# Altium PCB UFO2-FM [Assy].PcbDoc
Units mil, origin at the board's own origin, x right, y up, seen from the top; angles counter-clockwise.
Board outline 2125.98 x 1889.76 mil, 2 copper layers (Top Layer, Bottom Layer), stack 63.824 mil thick; 0 components, 51 nets, 0 pads, 0 vias.
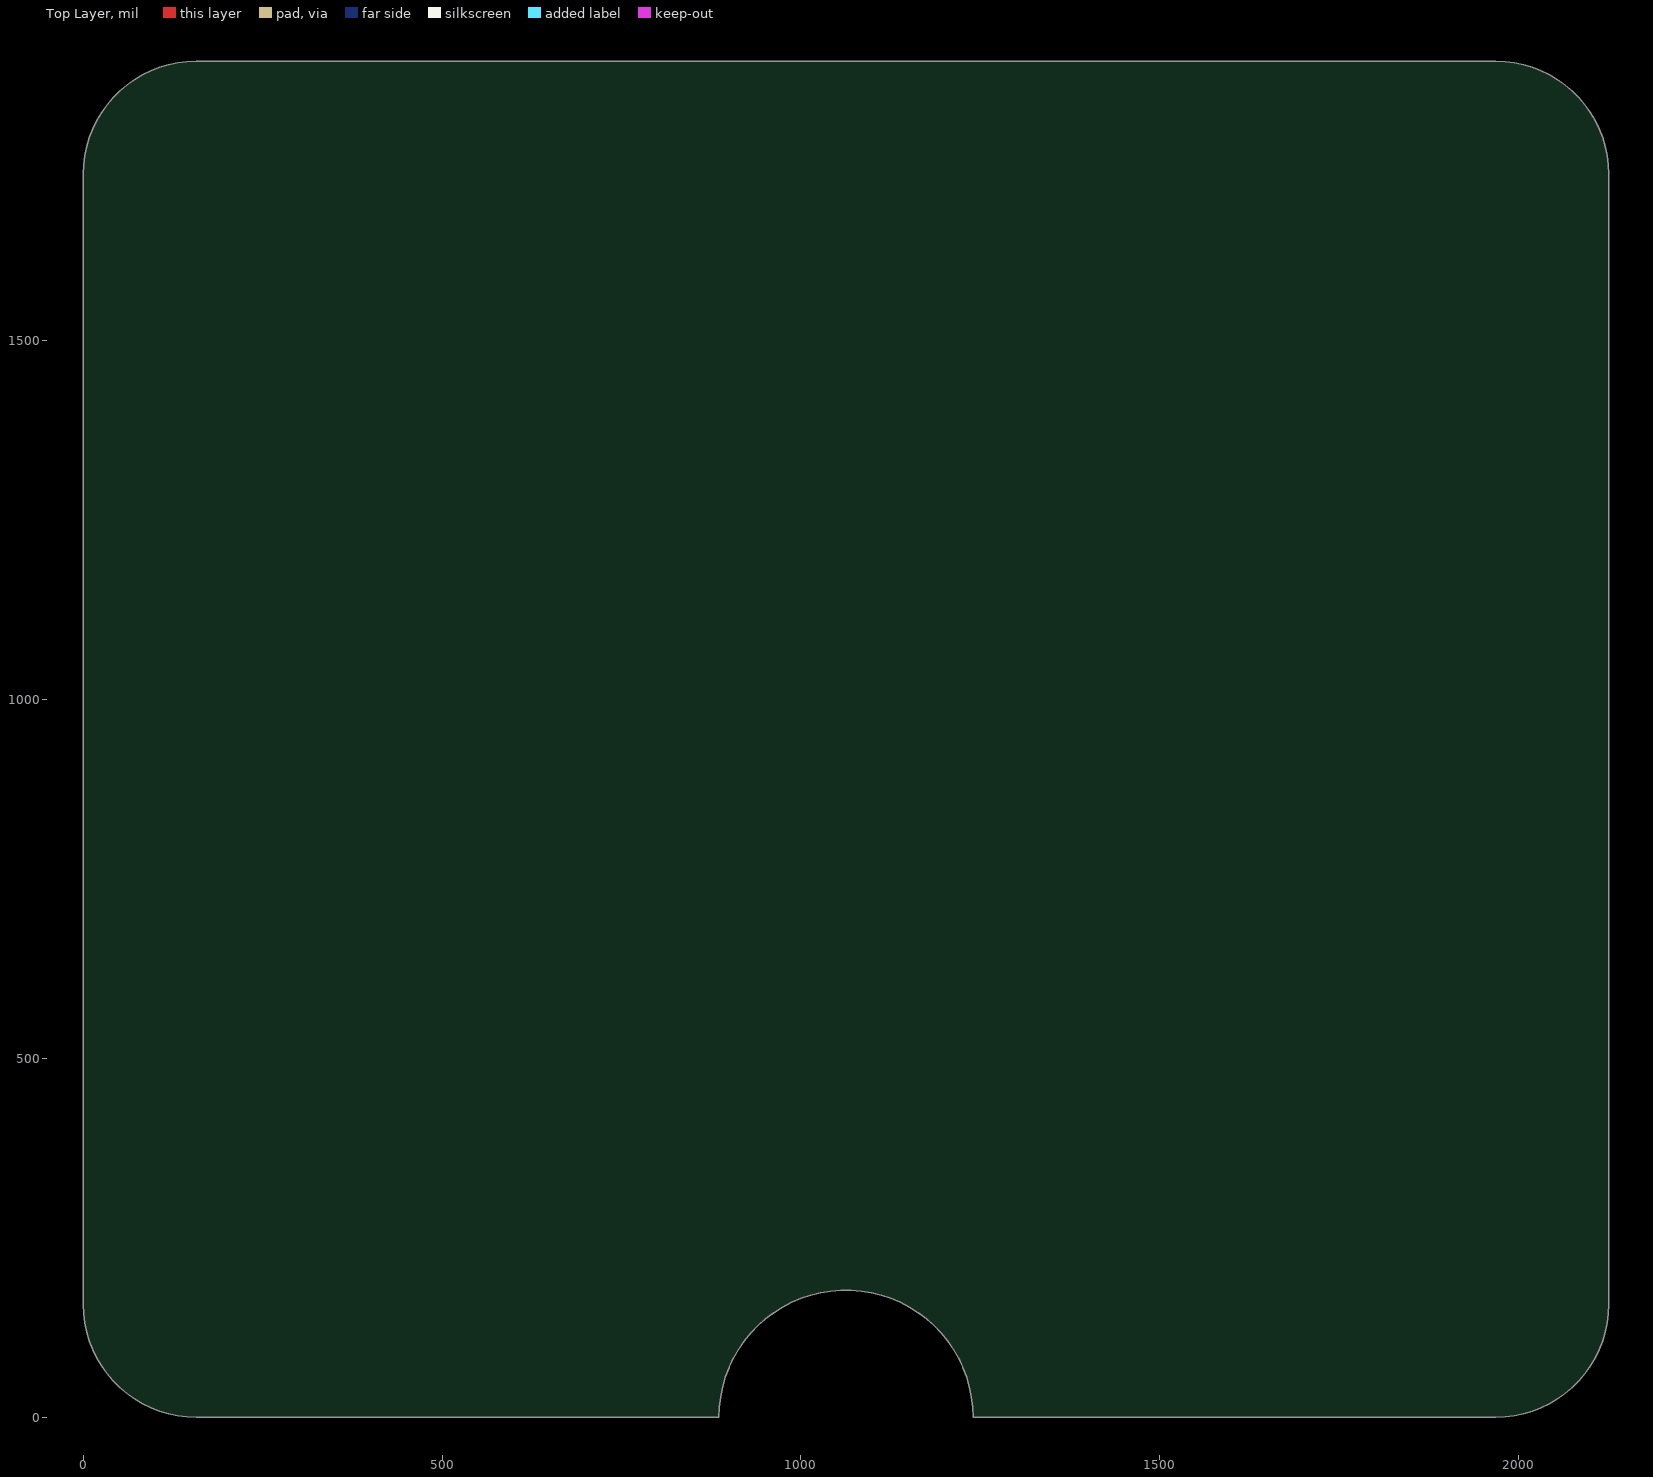
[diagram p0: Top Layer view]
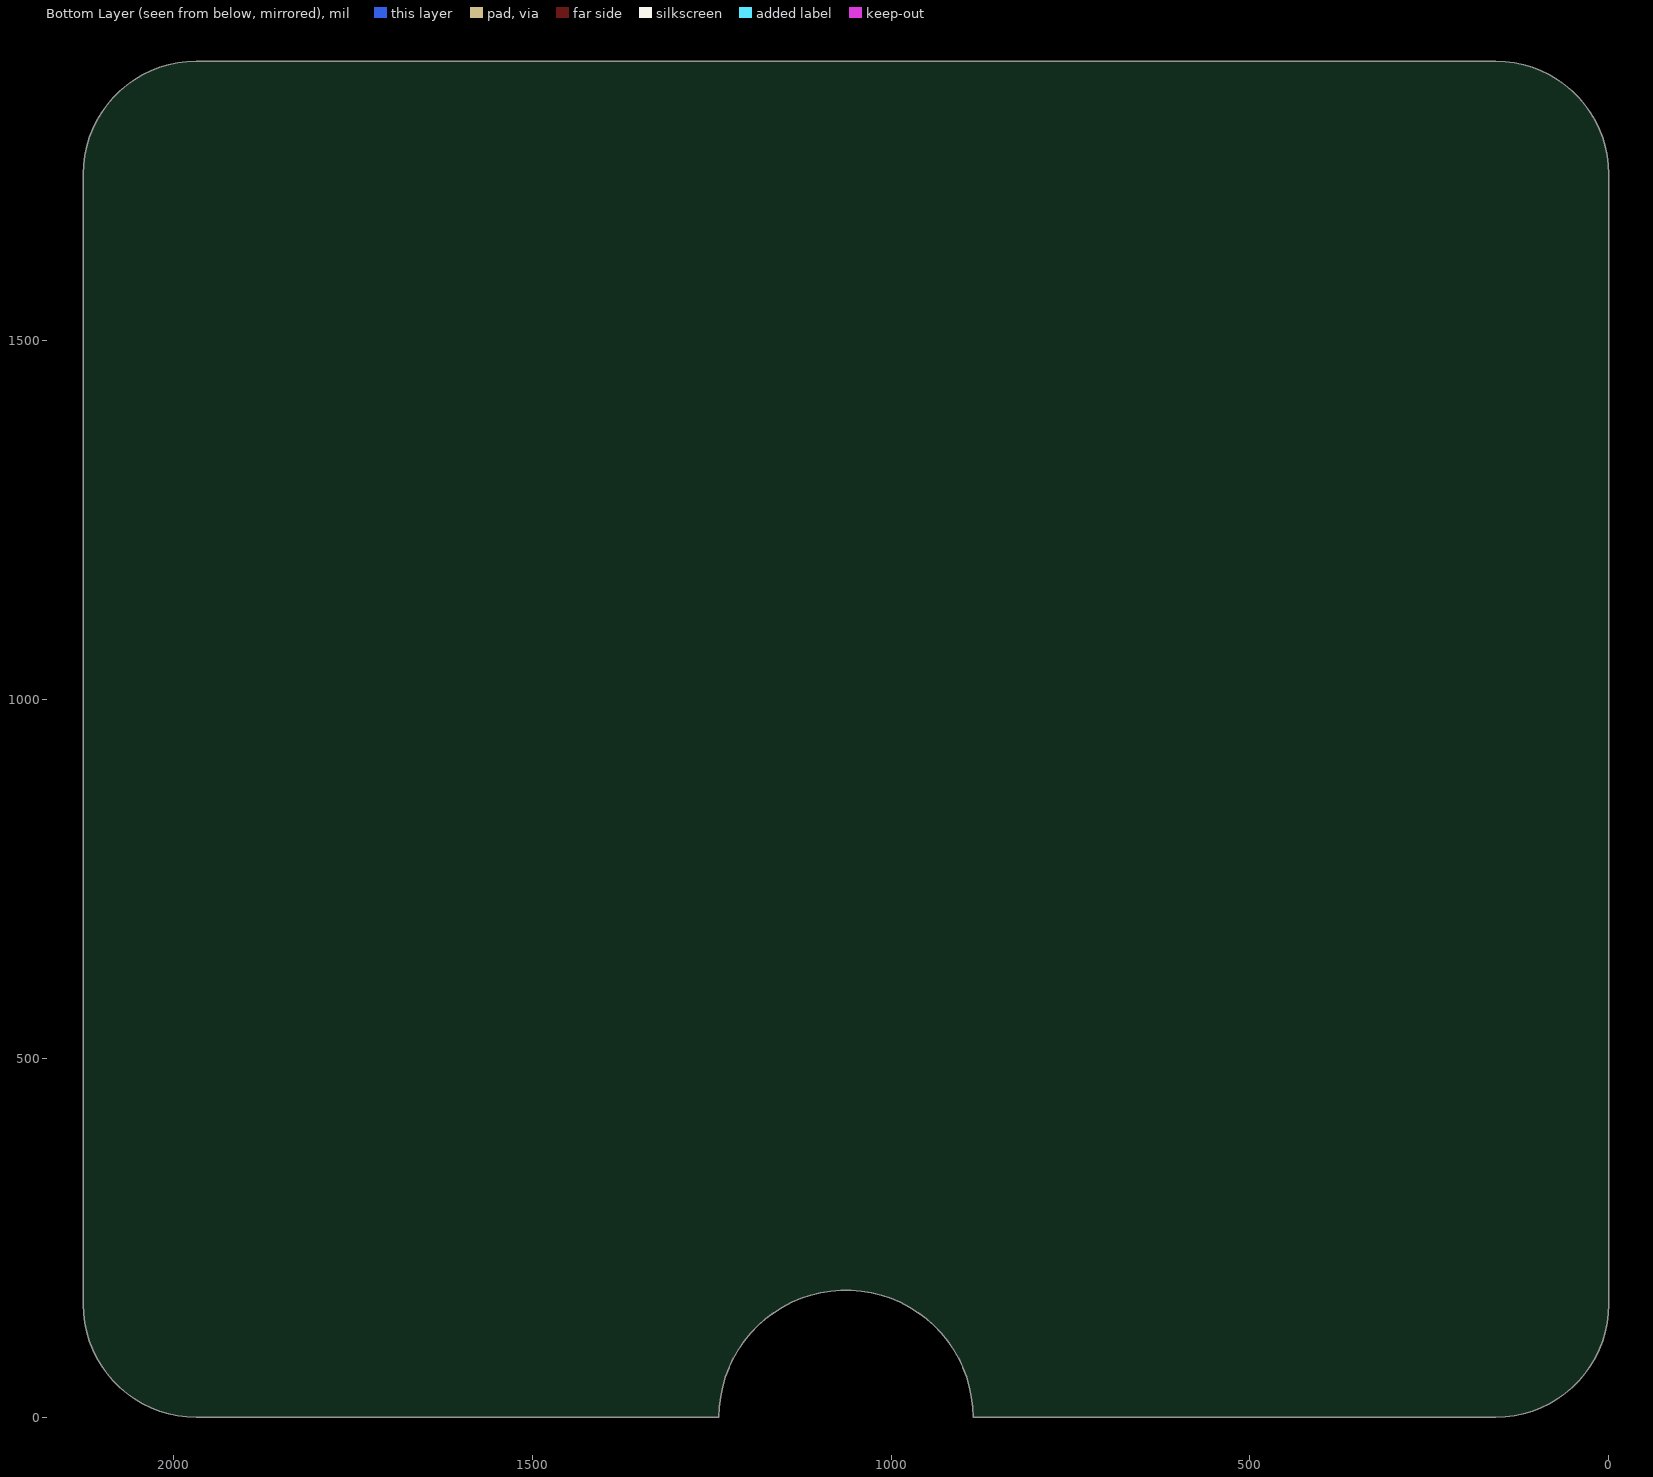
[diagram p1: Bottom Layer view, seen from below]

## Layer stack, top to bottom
Top Layer: signal copper 1.4
Dielectric: prepreg 61.0236, FR-4, Dk 4.2
Bottom Layer: signal copper 1.4

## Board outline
0,157.48 ccw(c157.48,157.48) 157.48,0 157.48,0.01 885.83,0 cw(c1062.99,0) 1240.16,0 1968.5,0 ccw(c1968.5,157.48) 2125.98,157.48 2125.98,1732.28 ccw(c1968.5,1732.28) 1968.5,1889.76 157.48,1889.76 ccw(c157.48,1732.28) 0,1732.28

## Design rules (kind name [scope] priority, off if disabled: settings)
Clearance [All] p1: gap=6.69
ComponentClearance [All] p1: gap=0 collisioncheckmode=3 verticalgap=1 showdistances=FALSE
FabricationTestPointUsage TestPointUsage [All] p1: valid=0 allowmultiple=FALSE
FabricationTestpoint Testpoint [All] p1: side=3 testpointundercomponent=TRUE minsize=40 maxsize=100 preferedsize=60 minholesize=0 maxholesize=40 preferedholesize=32 testpointgrid=1 allowsidetop=TRUE allowsidebottom=TRUE usegrid=TRUE gridtolerance=0.01
HoleSize [All] p1: absolutevalues=TRUE maxlimit=196.85 minlimit=9.84 maxpercent=80.000 minpercent=20.000
Length "Schematic Length Constraint_3" [InNet('TX3')] p1: maxlimit=2050 minlimit=2030
Length "Schematic Length Constraint_2" [InNet('TX2')] p2: maxlimit=2050 minlimit=2030
Length "Schematic Length Constraint_1" [InNet('TX1')] p3: maxlimit=2050 minlimit=2030
Length "Schematic Length Constraint" [InNet('TX0')] p4: maxlimit=2050 minlimit=2030
PlaneClearance [All] p1: clearance=19.68
PolygonConnect PolygonConnect_1 [All vs IsNamedPolygon('Bot - DGND-Direct')] p1: connectstyle=Direct reliefconductorwidth=10 reliefentries=4 polygonreliefangle="90 Angle" airgapwidth=10
PolygonConnect PolygonConnectVia [All vs isvia] p2: connectstyle=Direct reliefconductorwidth=9.84 reliefentries=4 polygonreliefangle="90 Angle" airgapwidth=10
PolygonConnect [All] p3: connectstyle=Relief reliefconductorwidth=15.75 reliefentries=4 polygonreliefangle="90 Angle" airgapwidth=10
RoutingCorners [All] p1: cornerstyle=45-Degree minsetback=98.43 maxsetback=98.43
RoutingVias [All] p1: holewidth=11.81 width=27.56 viastyle="Through Hole" minholewidth=11.81 minwidth=27.56 maxholewidth=11.81 maxwidth=27.56
ShortCircuit LK5 [(InNet('DGND') AND InComponent('LK5'))] p1: allowed=TRUE
ShortCircuit LK6 [(InNet('DGND') AND InComponent('LK6'))] p2: allowed=TRUE
ShortCircuit LK7 [(InNet('DGND') AND InComponent('LK7'))] p3: allowed=TRUE
ShortCircuit LK8 [(InNet('DGND') AND InComponent('LK8'))] p4: allowed=TRUE
ShortCircuit LK9 [(InNet('DGND') AND InComponent('LK9'))] p5: allowed=TRUE
ShortCircuit [All] p6: allowed=FALSE
SilkToSolderMaskClearance SilkscreenOverComponentPads [IsPad] p1: minsilkscreentomaskgap=10 clearancetoexposedcopper=TRUE
SolderMaskExpansion [All] p1: expansion=1.97
Width "Width_High Power" [InNetClass('High Power')] p1: maxlimit=59.06 minlimit=19.68 preferedwidth=39.37
Width Width_Power [InNetClass('Power')] p2: maxlimit=39.37 minlimit=11.81 preferedwidth=19.68
Width [All] p3: maxlimit=78.74 minlimit=7.87 preferedwidth=7.87
20 further rules are at their usual default settings.

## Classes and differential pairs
component class UFO2-FM: VDDD0-1V8

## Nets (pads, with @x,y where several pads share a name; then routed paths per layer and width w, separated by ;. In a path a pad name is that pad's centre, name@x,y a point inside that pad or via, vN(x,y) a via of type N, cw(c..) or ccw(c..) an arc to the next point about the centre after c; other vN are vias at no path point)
+3V3: 
+5V: 
DGND: 
MODE-BIT0: 
MODE-BIT1: 
NetBPON_1: 
NetBPOP_1: 
NetC16_1: 
NetC17_1: 
NetC18_1: 
NetC19_1: 
NetC24_1: 
NetC31_1: 
NetJ1_2: 
NetJ1_3: 
NetJ1_4: 
NetLED1_2: 
NetLED2_2: 
NetLK1_2: 
NetLK2_2: 
NetLK3_2: 
NetLK4_2: 
NetQ0_1: 
NetQ1_1: 
NetQ2_1: 
NetQ3_1: 
NetR17_2: 
NRESET: 
RTD_0: 
RTD_5: 
RTD_6: 
RTD_I: 
RXD0: 
SCL: 
SCLI: 
SDA: 
SDAI: 
TCK: 
TDA: 
TST: 
TX0: 
TX1: 
TX2: 
TX3: 
TXD0: 
VDD_IO: 
VDD_OSC: 
VDD_TX: 
VDDA: 
VDDD0: 
VIN: 

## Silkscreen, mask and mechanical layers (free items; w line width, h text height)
ACAD Top:
  circle w2: c1062.99,0 r177.17
Top Assy 1:
  circle w4.92: c0.04,-0.63 r78.74
  lines w7.87: -4103.15,-1961.3 -1859.06,-1961.3 ; -3611.02,-2158.15 -3611.02,-1961.3 ; -1859.06,-1764.45 1920.47,-1764.45 5503.15,-1764.45 ; -1859.06,-1567.6 1920.47,-1567.6 ; -1859.06,-1370.75 1920.47,-1370.75 ; -1859.06,-1173.9 1920.47,-1173.9 ; -1229.13,-2158.15 -1229.13,-977.05 ; -599.21,-977.05 -599.21,-2158.15 -599.21,-1961.3 ; -590.51,393.07 -511.77,393.07 ; -590.51,786.77 -511.77,786.77 ; -590.51,1179.37 -590.51,1967.87 ; -590.51,1180.47 -511.77,1180.47 ; -590.51,1574.17 -511.77,1574.17 ; -511.77,-0.63 -590.51,-0.63 -590.51,1967.87 ; -511.77,1967.87 -590.51,1967.87 ; -118.07,-0.63 -39.33,-0.63 ; 0.04,-512.44 0.04,-591.18 1180,-591.18 ; 0.04,-118.74 0.04,-40 ; 30.71,-2158.15 30.71,-977.05 ; 393.74,-591.18 393.74,-512.44 ; 660.63,-2158.15 660.63,-977.05 ; 787.44,-591.18 787.44,-512.44 ; 1181.14,-512.44 1181.14,-591.18 2361.1,-591.18 ; 1290.55,-2158.15 1290.55,-977.05 ; 1574.84,-591.18 1574.84,-512.44 ; 1968.54,-591.18 1968.54,-512.44 ; 2362.24,-591.18 2362.24,-512.44 ; 2629.13,-2158.15 2629.13,-1764.45 ; 4125.2,-2158.15 4125.2,-1764.45 ; 4637.01,-2158.15 4637.01,-1764.45 ; 5503.15,-1961.3 1920.47,-1961.3 1290.55,-1961.3 660.63,-1961.3 30.71,-1961.3 -599.21,-1961.3 ; -1859.06,-2158.15 -1859.06,-1961.3 ; -1859.06,-2158.15 -1859.06,-1961.3 ; -1859.06,-2158.15 -1859.06,-1961.3 ; -1859.06,-1961.3 -1229.13,-1961.3 -599.21,-1961.3 ; -1859.06,-1961.3 -1859.06,-977.05 ; -1859.06,-977.05 1920.47,-977.05 ; -1859.06,-977.05 -2488.98,-977.05 -4103.15,-977.05 -4103.15,-2158.15 1920.47,-2158.15 ; 1920.47,-2158.15 5503.15,-2158.15 5503.15,-977.05 1920.47,-977.05 ; 1920.47,-2158.15 1920.47,-977.05
  text "PLEASE MARK THE \"ISSUE\" BLOCK, ON THE PCB, WITH A" at -775,2700 h150
  text "PERMANENT-MARKER, AS INDICATED BELOW:" at -500,2550 h150
  text "ISSUE:" at 600,2350 h150
  text ".Version_PCB Assy Instruction" at 1058.36,2350 h157.48
  text "50" at -472.4,1928.5 h98.43
  text "40" at -472.4,1534.8 h98.43
  text "30" at -472.4,1141.1 h98.43
  text "20" at -472.4,747.4 h98.43
  text "10" at -472.4,353.7 h98.43
  text "0" at -472.4,-40 h98.43
  text "0" at 39.41,-473.07 h98.43 r90
  text "10" at 433.11,-473.07 h98.43 r90
  text "20" at 826.81,-473.07 h98.43 r90
  text "30" at 1220.51,-473.07 h98.43 r90
  text "40" at 1614.21,-473.07 h98.43 r90
  text "50" at 2007.91,-473.07 h98.43 r90
  text "60" at 2401.61,-473.07 h98.43 r90
  text "TITLE" at 1999.21,-1095.16 h98.43
  text "AGRIGEL" at -3936.83,-1348.07 h393.7
  text ".PCB_TITLE" at 2117.32,-1410.12 h196.85
  text "TOP SIDE PLACEMENT" at 2117.32,-1567.6 h98.43
  text ".PCB_Drawn" at -1701.57,-1882.56 h98.43
  text ".PCB_Checked" at -1111.02,-1882.56 h98.43
  text ".PCB_Approved" at -481.1,-1882.56 h98.43
  text ".PRINT_DATE" at 148.82,-1882.56 h98.43
  text ".PCB_DocRevision" at 900,-1882.56 h98.43
  text ".PCB_ECRNo" at 1448.03,-1882.56 h98.43
  text "DWG NUMBER" at 1959.84,-1882.56 h98.43
  text ".PCB_Drawing Number" at 2707.87,-1882.56 h98.43
  text "PCB VER" at 4164.57,-1882.56 h98.43
  text "SHEET NO." at 4715.75,-1882.56 h98.43
  text "PLOTFILE" at -4063.78,-2079.41 h98.43
  text ".PCB_Plot File [Assy]" at -3571.65,-2079.41 h98.43
  text "DRAWN" at -1701.57,-2079.41 h98.43
  text "CHECKED" at -1111.02,-2079.41 h98.43
  text "APPROVED" at -520.47,-2079.41 h98.43
  text "DATE" at 227.56,-2079.41 h98.43
  text "DOC REV." at 778.74,-2079.41 h98.43
  text "ECR NO." at 1448.03,-2079.41 h98.43
  text "SOURCE" at 1959.84,-2079.41 h98.43
  text ".Pcb_File_Name_No_Path" at 2707.87,-2079.41 h98.43
  text ".Version" at 4243.31,-2079.41 h98.43
  text "SHEET" at 4715.75,-2079.41 h98.43
  text "1" at 5070.08,-2079.41 h98.43
  text "OF" at 5188.19,-2079.41 h98.43
  text "1" at 5385.04,-2079.41 h98.43

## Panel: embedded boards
"UFO2-FM.PcbDoc" at -0.78,-0.78, 1 rows x 1 columns, spacing 1990 x 2225.98, rotation 0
